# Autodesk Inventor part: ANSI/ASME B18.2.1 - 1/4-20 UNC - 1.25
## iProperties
Comments: To add or edit properties for Autodesk Inventor files, use iProperties.
Created: 2005-06
Part Number: ANSI/ASME B18.2.1 - 1/4-20 UNC - 1.25
Vendor: Autodesk Inc.
Document SubType Name: Modeling
Designer: John Blackburn
Material: Default
Description: Hex Bolt - UNC (Regular Thread - Inch)
Standard: ANSI/ASME B18.2.1
Alert: To add or edit properties for Autodesk Inventor files, use iProperties.
Control State: 0
Master: False
Checked Out: False
Shininess: 64.0
Length Units: 11272
Angle Units: 11279
Time Units: 11290
Mass Units: 11286
Length Display Precision: 3
Angle Display Precision: 2
Compacted: True
EGR: 3
Classification: un/spsc 31161513
Density: 0.0
Volumn: 0.0
Area: 0.0
PropertySet Name: Model Information
Author: John Blackburn
Revision Number: 8
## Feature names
1. Body [Revolution]
2. Head [Extrusion]
3. Chamfer1 [Revolution]
4. Chamfer2
